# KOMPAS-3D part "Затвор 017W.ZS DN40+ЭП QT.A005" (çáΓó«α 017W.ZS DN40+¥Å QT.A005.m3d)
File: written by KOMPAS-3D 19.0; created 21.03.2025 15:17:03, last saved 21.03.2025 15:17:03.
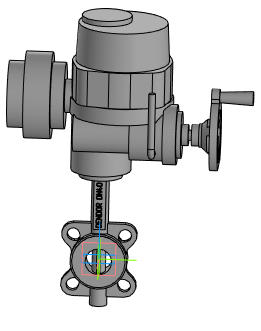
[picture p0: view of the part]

Document properties: Полное имя файла: Затвор 017W.ZS DN40+ЭП QT.A005.a3d

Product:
- Part/product: Затвор 017W.ZS DN40+ЭП QT.A005
    Масса: 38.0675

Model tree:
1. Операция без истории:1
